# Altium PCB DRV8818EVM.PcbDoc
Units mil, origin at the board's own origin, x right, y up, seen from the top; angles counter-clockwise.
Board outline 4500 x 5500 mil, 6 copper layers (Top Layer, Kelvin, MidLayer2, GND, InternalPlane2, Bottom Layer); 107 components, 80 nets, 344 pads, 137 vias.
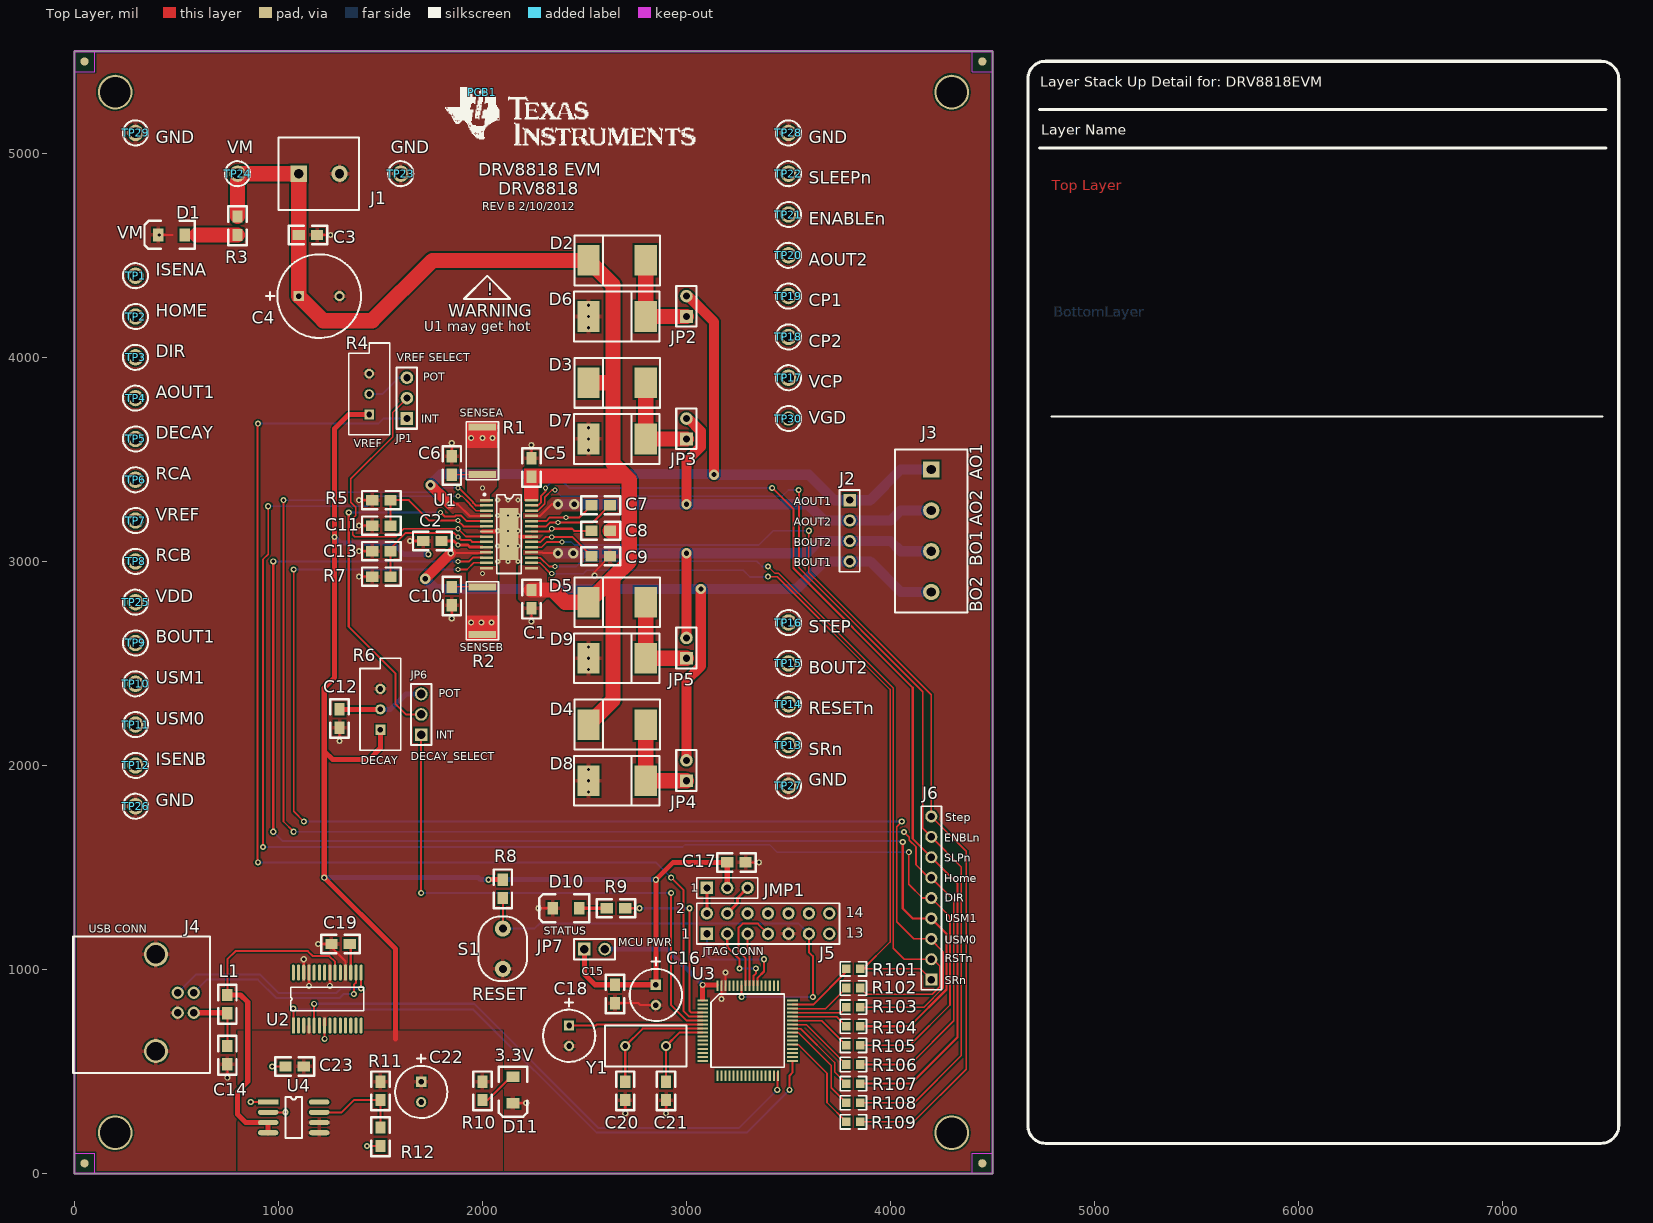
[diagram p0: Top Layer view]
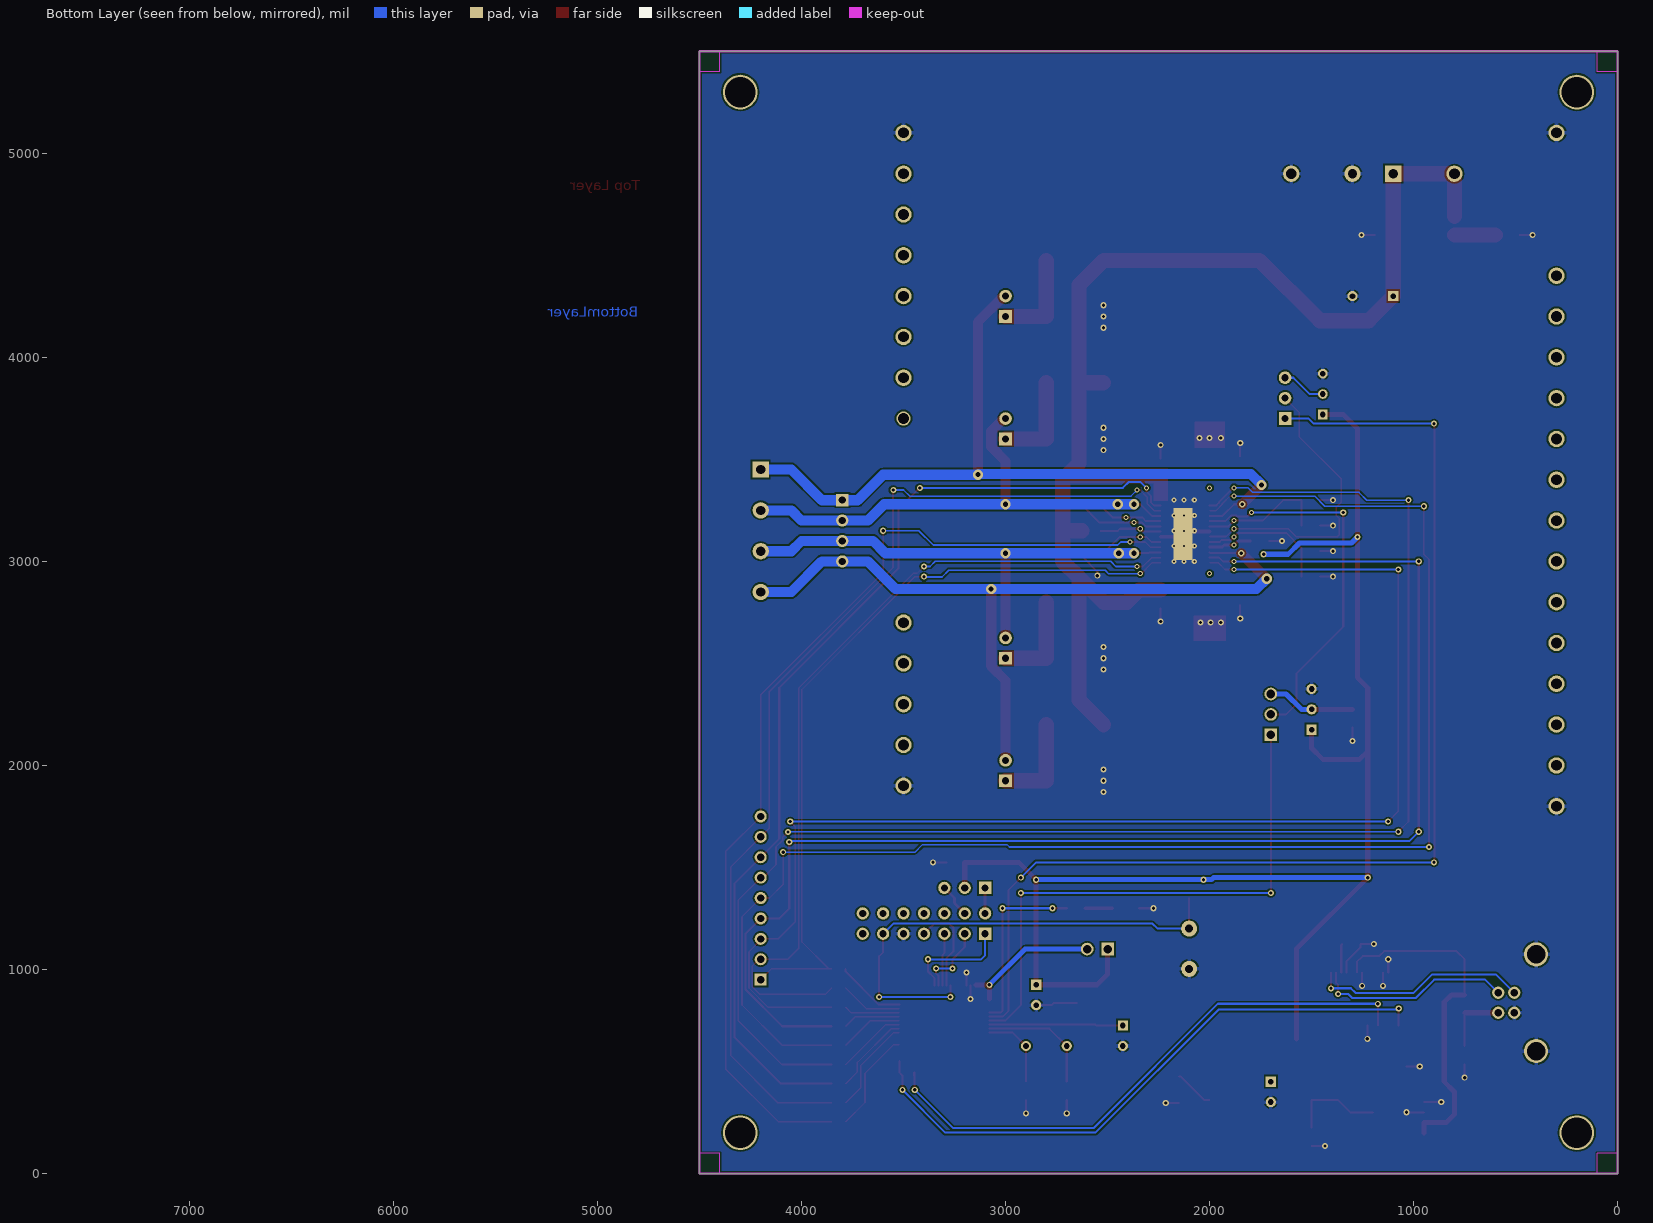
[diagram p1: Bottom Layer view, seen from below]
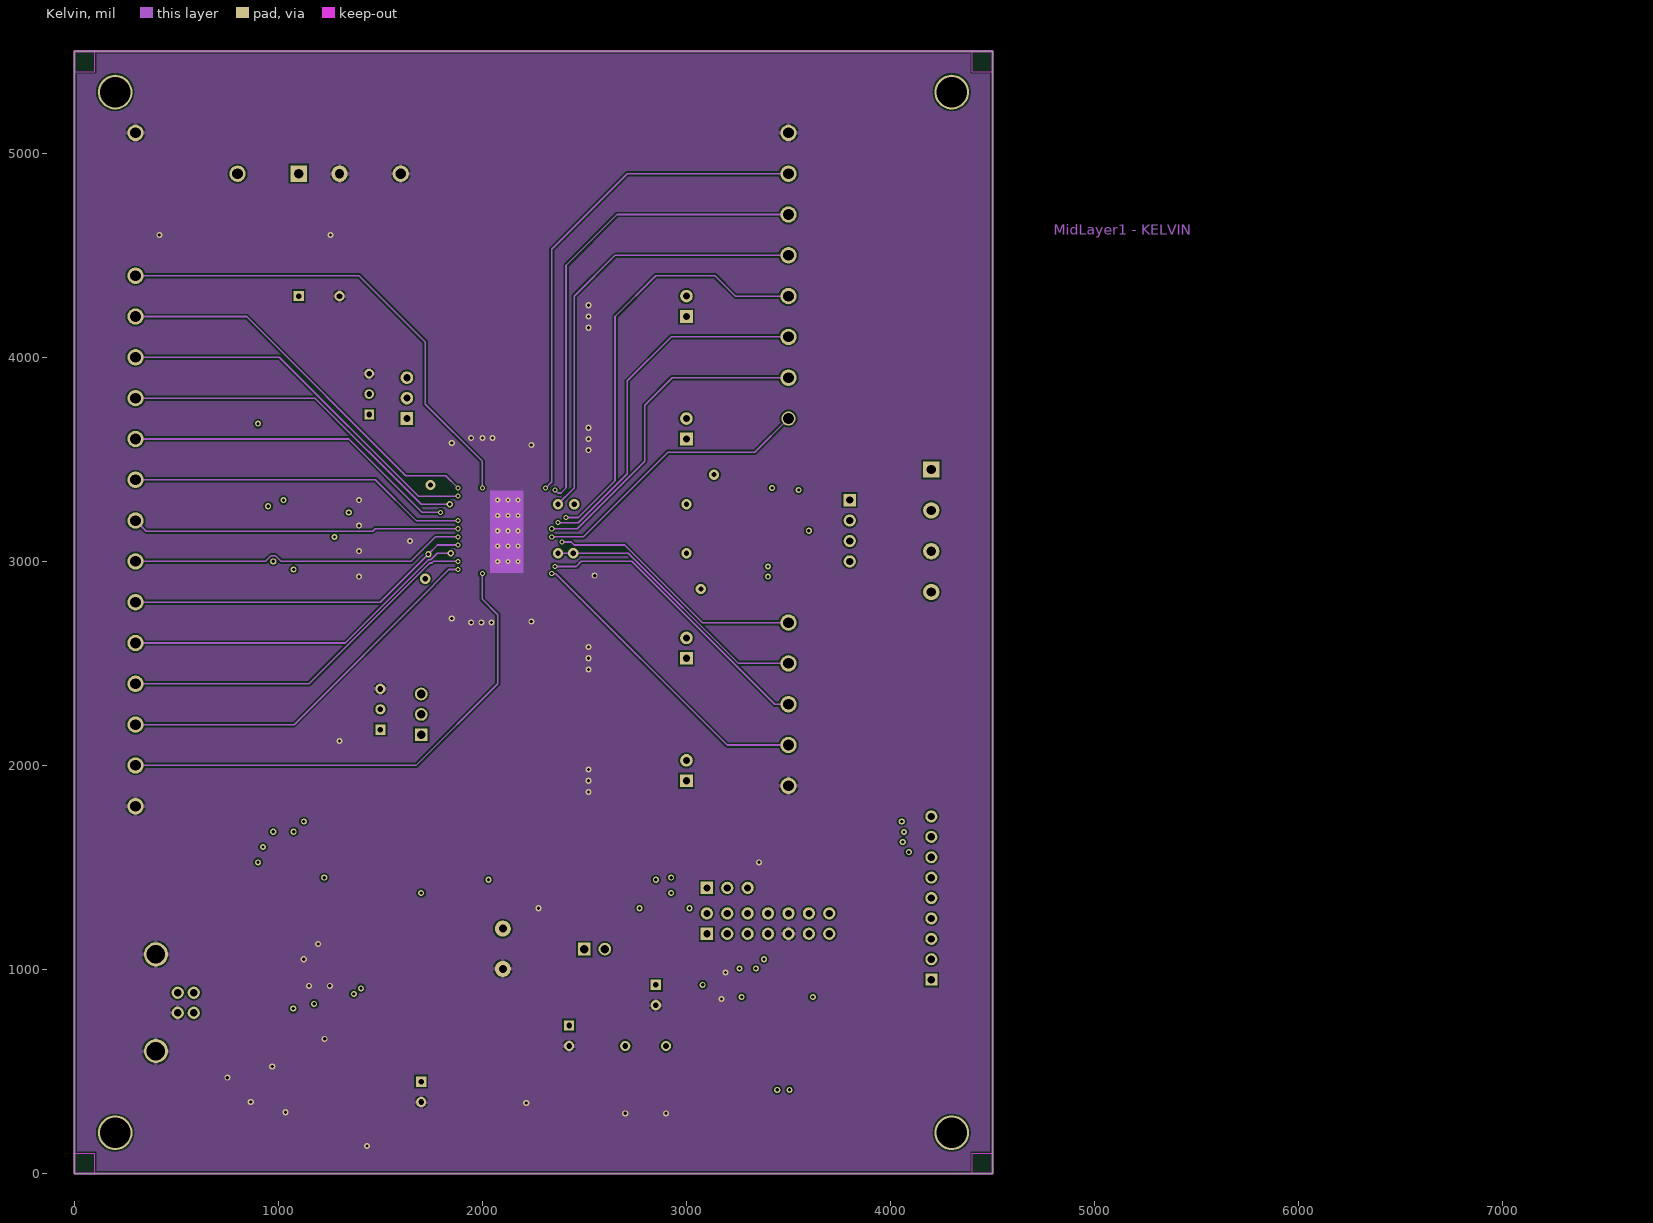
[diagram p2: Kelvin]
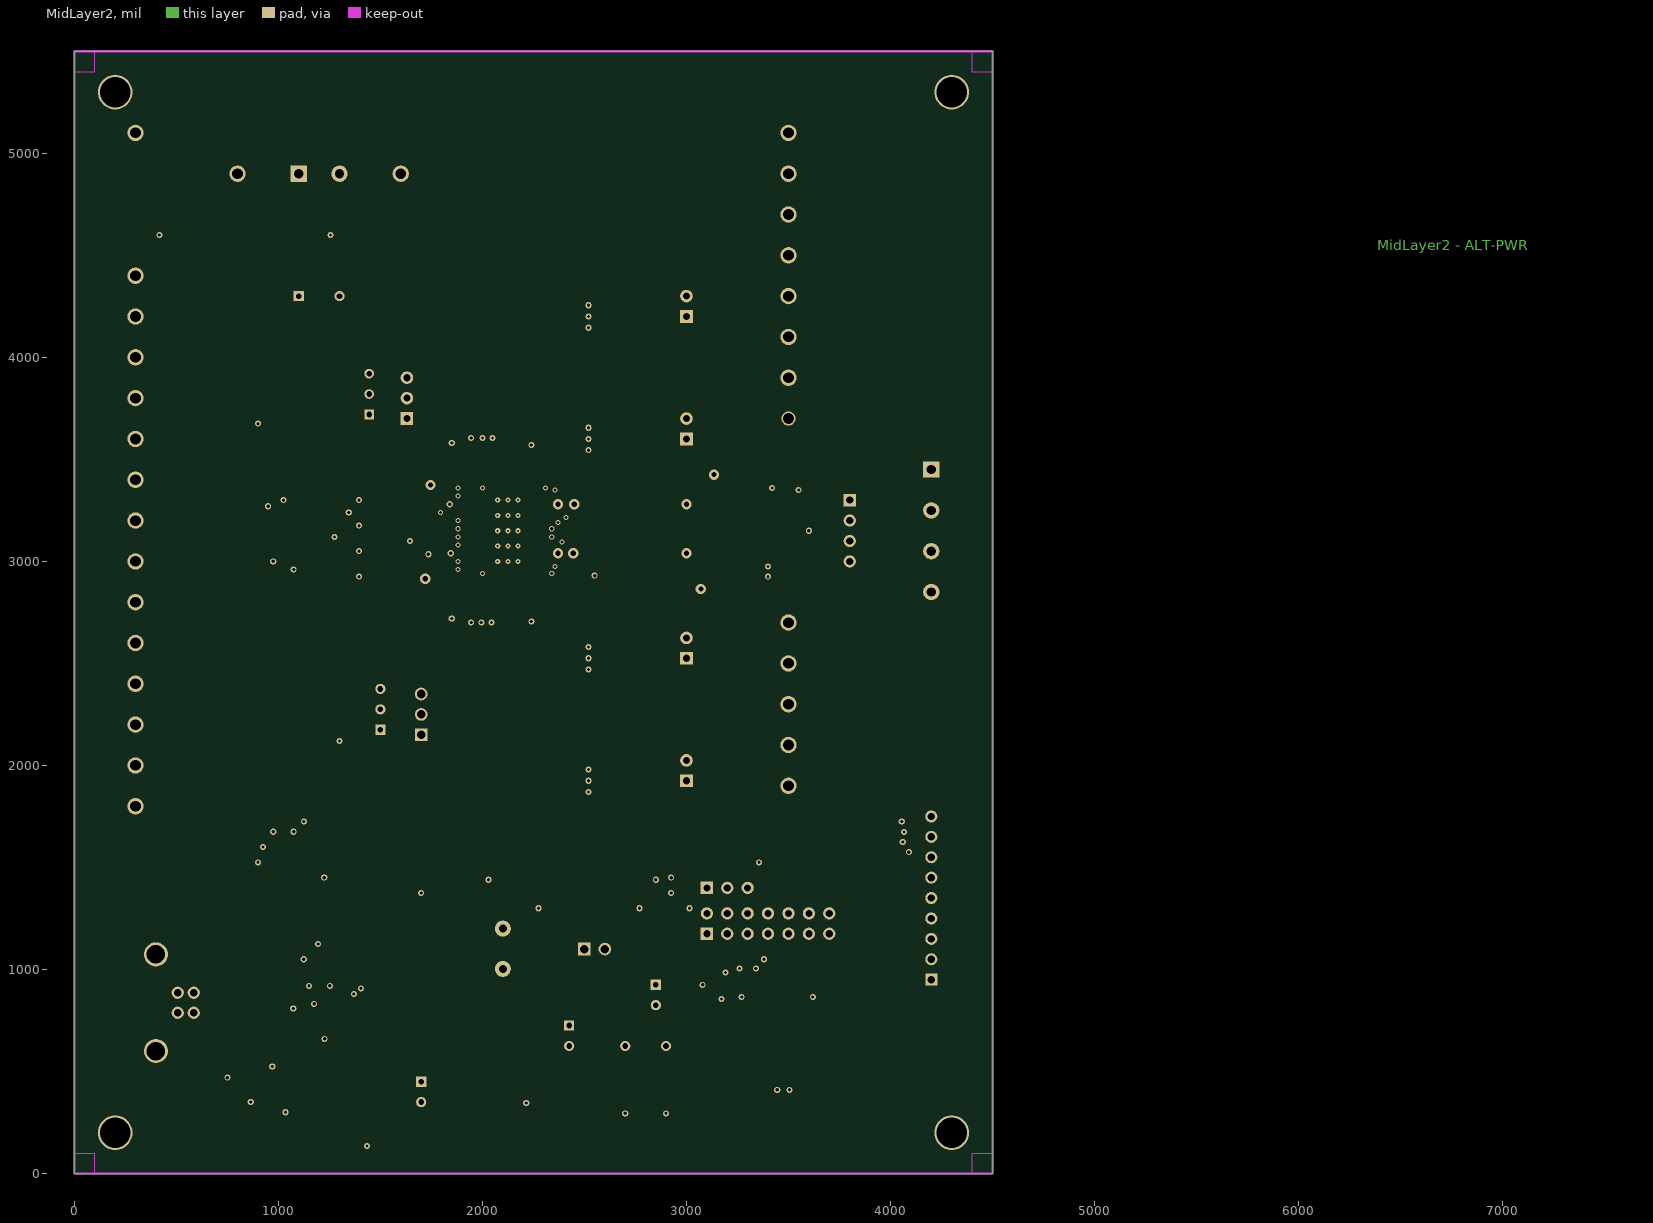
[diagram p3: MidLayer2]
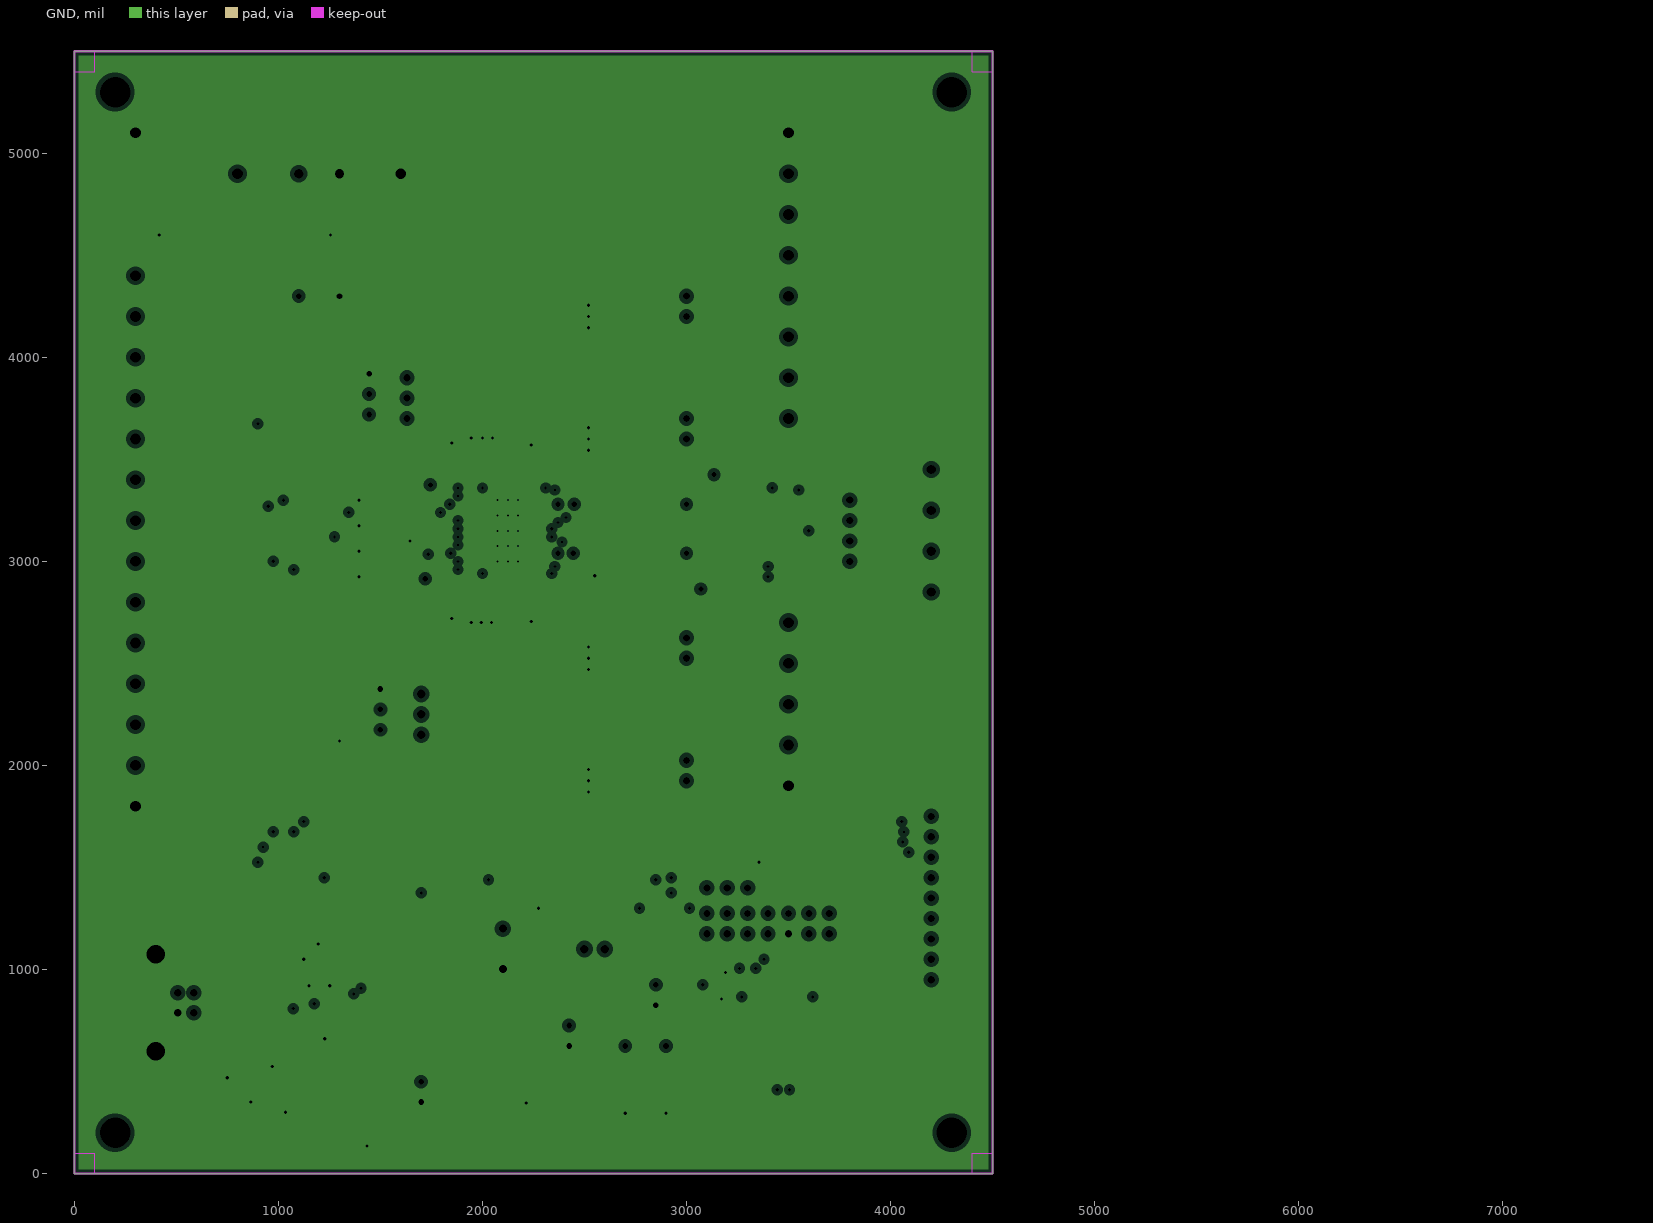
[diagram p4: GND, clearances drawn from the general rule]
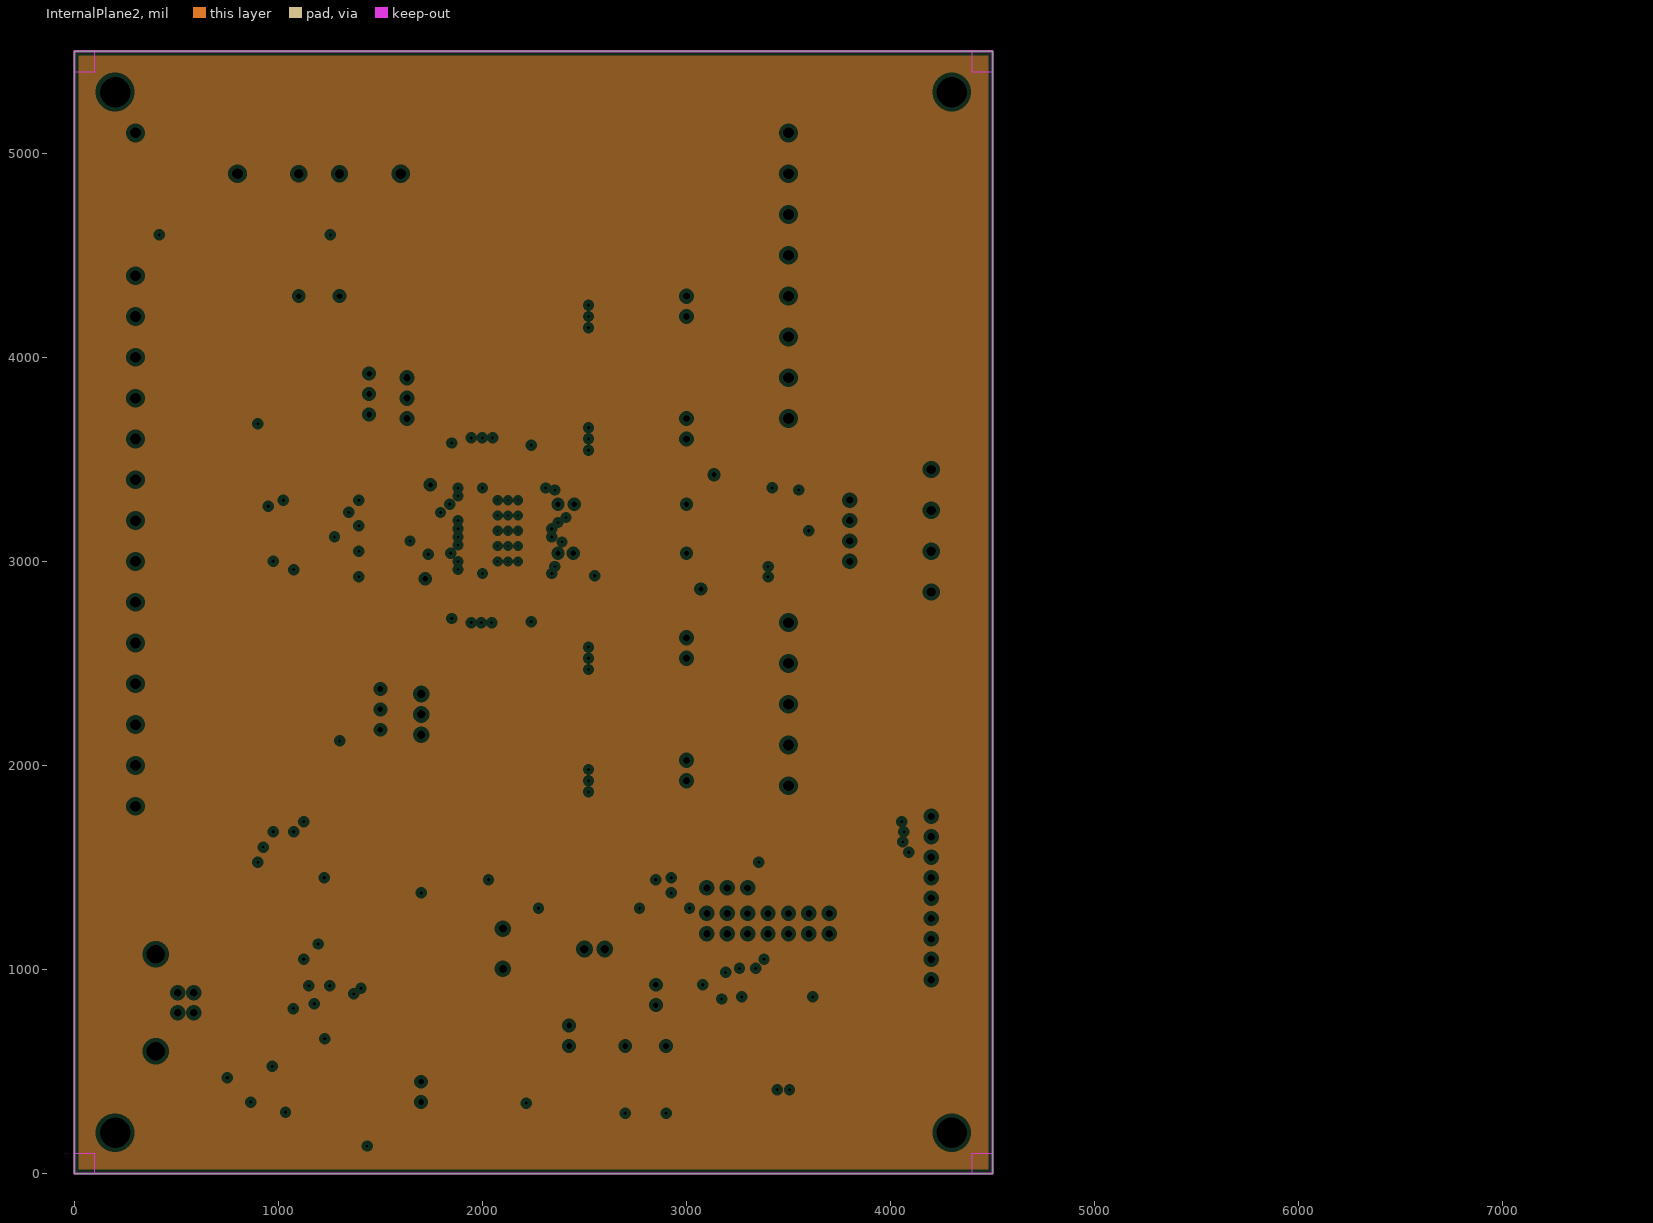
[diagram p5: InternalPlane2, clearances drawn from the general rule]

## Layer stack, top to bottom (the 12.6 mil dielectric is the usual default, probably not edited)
Top Layer: signal copper 1.4
Dielectric: core 12.6, FR-4, Dk 4.8
Kelvin: signal copper 1.4
Dielectric: prepreg 12.6, FR-4, Dk 4.8
MidLayer2: signal copper 1.4
Dielectric: dielectric 12.6, FR-4, Dk 4.8
GND: plane copper 1.4, net GND
Dielectric: core 12.6, FR-4, Dk 4.8
InternalPlane2: plane copper 1.4
Dielectric: dielectric 12.6, FR-4, Dk 4.8
Bottom Layer: signal copper 1.4

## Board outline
0,0 4500,0 4500,5500 0,5500

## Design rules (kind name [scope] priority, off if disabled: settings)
Clearance Clearance_1 [InNamedPolygon('Top Layer-MGND') Or  InNamedPolygon('Bottom Layer-OD_C_REG') Or  InNamedPolygon('Bottom Layer-OD_A_REG') Or  InNamedPolygon('Bottom Layer-OD_B_REG') Or  InNamedPolygon('Bottom Layer-MGND')] p1: gap=15
Clearance [All] p2: gap=8
HoleSize [All] p1: absolutevalues=TRUE maxlimit=360 minlimit=1 maxpercent=80.000 minpercent=20.000
MinimumAnnularRing [All] p1: minimumring=5
PlaneClearance [All] p1: clearance=20
PlaneConnect [All] p1: planeconnectstyle=Relief reliefexpansion=20 reliefentries=4 reliefconductorwidth=15 reliefairgap=10
PolygonConnect PolygonConnect_2 [(InNet('GND')) vs IsVia  or InComponent('U1')] p1: connectstyle=Direct reliefconductorwidth=10 reliefentries=4 polygonreliefangle="90 Angle"
PolygonConnect PolygonConnect_1 [All vs IsNamedPolygon('ISENA') Or  IsNamedPolygon('ISENB') Or  IsNamedPolygon('AOUT2') Or  IsNamedPolygon('BOUT2') Or  IsNamedPolygon('BOUT1') Or  IsNamedPolygon('AOUT1') Or  IsNamedPolygon('VMB') Or  IsNamedPolygon('VMA')] p2: connectstyle=Direct reliefconductorwidth=10 reliefentries=4 polygonreliefangle="90 Angle"
PolygonConnect [All] p3: connectstyle=Relief reliefconductorwidth=20 reliefentries=4 polygonreliefangle="90 Angle"
RoutingLayers [All] p1: top layer_v5=TRUE mid layer 1_v5=FALSE mid layer 2_v5=FALSE bottom layer_v5=TRUE
RoutingVias [All] p1: holewidth=16 width=30 viastyle="Through Hole" minholewidth=16 minwidth=25 maxholewidth=25 maxwidth=70
SilkscreenOverComponentPads [All] p1: minsilkscreentomaskgap=10
SolderMaskExpansion [All] p1: expansion=4
TestPointUsage [All] p1: valid=2 allowmultiple=FALSE
Testpoint [All] p1: side=15 testpointundercomponent=TRUE minsize=40 maxsize=100 preferedsize=60 minholesize=0 maxholesize=40 preferedholesize=32 testpointgrid=1 style=1023 order=0-112345678
Width [All] p1: maxlimit=100 minlimit=8 preferedwidth=8 toplayer_prefwidth=10 midlayer1_maxwidth=8 midlayer2_maxwidth=8 bottomlayer_prefwidth=50 minimp=50.000000 maximp=50.000000 favimp=50.000000
19 further rules are at their usual default settings.

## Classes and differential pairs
polygon class PinPolygons: Bottom-GND VDD

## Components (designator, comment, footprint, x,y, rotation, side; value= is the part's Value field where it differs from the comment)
C1 "" 0805 2240,2770 r90 top
C2 "" 0805 1710,3100 r0 top
C3 "" 0805 1190,4600 r180 top
C4 "" "RB .2/.4 SS" 1300,4300 r180 top
C5 "" 0805 2240,3505 r270 top
C6 "" 0805 1850,3515 r270 top
C7 ".1uF" 0805 2625,3275 r180 top
C8 ".1uF" 0805 2625,3150 r180 top
C9 ".1uF" 0805 2625,3025 r180 top
C10 "" 0805 1850,2785 r90 top
C11 "" 0805 1550,3175 r180 top
C12 "" 0805 1300,2275 r270 top
C13 "" 0805 1550,3050 r180 top
C14 "Cap" 0805 750,535 r90 top
C15 "Cap" 0805 2650,835 r90 top
C16 "Cap Pol1" "RB .1/.250" 2850,825 r270 top
C17 "Cap" 0805 3290,1525 r180 top
C18 "Cap Pol1" "RB .1/.250" 2425,625 r270 top
C19 "Cap" 0805 1260,1125 r0 top
C20 "Cap" 0805 2700,360 r90 top
C21 "Cap" 0805 2900,360 r90 top
C22 "Cap Pol1" "RB .1/.250" 1700,350 r270 top
C23 "Cap1" 0805 1035,525 r0 top
D1 "VBB" 1206_LED 540.94,4600 r180 top
D2 "MBRS360" SMC-W 2800,4475 r180 top
D3 "MBRS360" SMC-W 2800,3875 r180 top
D4 "MBRS360" SMC-W 2800,2200 r180 top
D5 "MBRS360" SMC-W 2800,2800 r180 top
D6 "MBRS360" SMC-W 2520,4200 r0 top
D7 "MBRS360" SMC-W 2520,3600 r0 top
D8 "MBRS360" SMC-W 2520,1925 r0 top
D9 "MBRS360" SMC-W 2520,2525 r0 top
D10 "LED3" 1206_LED 2475,1300 r180 top
D11 "LED3" 1206_LED 2150,475 r270 top
J1 "Header 2" PWR_CONN2 1100,4900 r0 top
J2 "Header 4" HDR1X4 3800,3300 r270 top
J3 "Header 4" PWR_CONN4 4200,3450 r270 top
J4 "USB B Conn" USB_CONN 506.69,886.22 r270 top
J5 "JTAG" HDR2X7 3100,1175 r0 top
J6 "Header 9" HDR1X9 4200,950 r90 top
JMP1 "PWR Select" HDR1X3 3100,1400 r0 top
JP1 "VREF_SELECT" JMP0.3#1 1630,3700 r90 top
JP2 "JUMPER 2 PIN" JMP0.2#1 3000,4200 r90 top
JP3 "JUMPER 2 PIN" JMP0.2#1 3000,3600 r90 top
JP4 "JUMPER 2 PIN" JMP0.2#1 3000,1925 r90 top
JP5 "JUMPER 2 PIN" JMP0.2#1 3000,2525 r90 top
JP6 "DECAY_SELECT" JMP0.3#2 1700,2150 r90 top
JP7 "MCU PWR" JMP0.2#2 2500,1100 r0 top
L1 "" 0805 750,785 r90 top
PCB1 "DRV8818" TI_LOGO 2000,5300 r0 top
R1 "" 2512 2000,3425 r90 top
R2 "" 2512 2000,2875 r270 top
R3 "Res1" 0805 800,4600 r90 top
R4 "" VR5#1 1445,3820 r90 top
R5 "" 0805 1460,3300 r0 top
R6 "" VR5#2 1500,2275 r90 top
R7 "" 0805 1460,2925 r0 top
R8 "Res1" 0805 2100,1350 r90 top
R9 "Res2" 0805 2610,1300 r0 top
R10 "Res2" 0805 2000,360 r90 top
R11 "Res2" 0805 1500,360 r90 top
R12 "Res2" 0805 1500,135 r90 top
R101 "Res2" 0603 3852,1003 r180 top
R102 "Res2" 0603 3852,909.25 r180 top
R103 "Res2" 0603 3852,815.5 r180 top
R104 "Res2" 0603 3852,721.75 r180 top
R105 "Res2" 0603 3852,628 r180 top
R106 "Res2" 0603 3852,534.25 r180 top
R107 "Res2" 0603 3852,440.5 r180 top
R108 "Res2" 0603 3852,346.75 r180 top
R109 "Res2" 0603 3852,253 r180 top
S1 "SW-PB" Pana_PB 2100,1003.15 r90 top
TP1 "ISENA" "TEST POINT 0.052"#1 300,4400 r0 top
TP2 "HOME" "TEST POINT 0.052"#1 300,4200 r0 top
TP3 "DIR" "TEST POINT 0.052"#1 300,4000 r0 top
TP4 "AOUT1" "TEST POINT 0.052"#1 300,3800 r0 top
TP5 "DECAY" "TEST POINT 0.052"#1 300,3600 r0 top
TP6 "RCA" "TEST POINT 0.052"#1 300,3400 r0 top
TP7 "VREF" "TEST POINT 0.052"#1 300,3200 r0 top
TP8 "RCB" "TEST POINT 0.052"#1 300,3000 r0 top
TP9 "BOUT1" "TEST POINT 0.052"#1 300,2600 r0 top
TP10 "USM1" "TEST POINT 0.052"#1 300,2400 r0 top
TP11 "USM0" "TEST POINT 0.052"#1 300,2200 r0 top
TP12 "ISENB" "TEST POINT 0.052"#1 300,2000 r0 top
TP13 "SRn" "TEST POINT 0.052"#1 3500,2100 r0 top
TP14 "RESETn" "TEST POINT 0.052"#1 3500,2300 r0 top
TP15 "BOUT2" "TEST POINT 0.052"#1 3500,2500 r0 top
TP16 "STEP" "TEST POINT 0.052"#1 3500,2700 r0 top
TP17 "VCP" "TEST POINT 0.052"#1 3500,3900 r0 top
TP18 "CP2" "TEST POINT 0.052"#1 3500,4100 r0 top
TP19 "CP1" "TEST POINT 0.052"#1 3500,4300 r90 top
TP20 "AOUT2" "TEST POINT 0.052"#1 3500,4500 r0 top
TP21 "ENABLEn" "TEST POINT 0.052"#1 3500,4700 r90 top
TP22 "SLEEPn" "TEST POINT 0.052"#1 3500,4900 r90 top
TP23 "GND" "TEST POINT 0.052"#1 1600,4900 r90 top
TP24 "VM" "TEST POINT 0.052"#1 800,4900 r90 top
TP25 "VDD" "TEST POINT 0.052"#1 300,2800 r90 top
TP26 "GND" "TEST POINT 0.052"#1 300,1800 r0 top
TP27 "GND" "TEST POINT 0.052"#1 3500,1900 r90 top
TP28 "GND" "TEST POINT 0.052"#1 3500,5100 r90 top
TP29 "GND" "TEST POINT 0.052"#1 300,5100 r90 top
TP30 "VGD" "TEST POINT 0.052"#2 3500,3700 r90 top
U1 "DRV8818" "HTSSOP28 - DRV8818" 2019.69,3300 r270 top
U2 "FTD232R" FT232RL 1073.23,725 r90 top
U3 "MSP430F2917" MSP430F1612 3300,700 r0 top
U4 "TPS77701" TL7726 950,350 r0 top
Y1 "8 MHZ" XTAL 2900,625 r180 top

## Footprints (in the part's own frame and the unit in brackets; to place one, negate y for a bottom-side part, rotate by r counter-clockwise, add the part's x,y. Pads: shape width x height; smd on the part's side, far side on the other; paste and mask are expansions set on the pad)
0603 [mm]
  rect 1.05x1.08 smd: 1(0,0) 2(1.73,0)
  silkscreen extent -0.77,-0.89 2.5,0.89
0805 [mil]
  rect 60x50 smd: 1(0,0) 2(90,0)
  silkscreen extent -50,-45 140,45
1206_LED [mm]
  rect 1.3x1.6 smd: 1(0,0) 2(3.3,0)
  silkscreen extent -1.25,-1.75 5,1.75
2512 [mm]
  rect 0.85x3.4 smd: 1(0,0) 2(5.93,0)
  silkscreen extent -0.64,-2 6.57,2
FT232RL [mm]
  rect 2x0.381 smd: 1(0,0)
  oval 2x0.381 smd: 2(0,-0.65) 3(0,-1.3) 4(0,-1.95) 5(0,-2.6) 6(0,-3.25) 7(0,-3.9) 8(0,-4.55) 9(0,-5.2) 10(0,-5.85) 11(0,-6.5) 12(0,-7.15) 13(0,-7.8) 14(0,-8.45) 15(6.6,-8.45) 16(6.6,-7.8) 17(6.6,-7.15) 18(6.6,-6.5) 19(6.6,-5.85) 20(6.6,-5.2) 21(6.6,-4.55) 22(6.6,-3.9) 23(6.6,-3.25) 24(6.6,-2.6) 25(6.6,-1.95) 26(6.6,-1.3) 27(6.6,-0.65) 28(6.6,0)
  silkscreen extent 1.84,-8.78 4.76,0.33
HDR1X3 [mil] "Connector; Header; 3 Position"
  rect 60x60 hole 35: 1(0,0)
  round 60 hole 35: 2(100,0) 3(200,0)
  silkscreen extent -50,-50 250,50
HDR1X4 [mil] "Connector; Header; 4 Position"
  rect 60x60 hole 35: 1(0,0)
  round 60 hole 35: 2(100,0) 3(200,0) 4(300,0)
  silkscreen extent -50,-50 350,50
HDR1X9 [mm] "Connector; Header; 9 Position"
  rect 1.5x1.5 hole 0.9: 1(0,0)
  round 1.5 hole 0.9: 2(2.54,0) 3(5.08,0) 4(7.62,0) 5(10.16,0) 6(12.7,0) 7(15.24,0) 8(17.78,0) 9(20.32,0)
  silkscreen extent -1.27,-1.27 21.59,1.27
HDR2X7 [mil] "Connector; Header; 7x2 Position"
  rect 60x60 hole 35: 1(0,0)
  round 60 hole 35: 2(0,100) 3(100,0) 4(100,100) 5(200,0) 6(200,100) 7(300,0) 8(300,100) 9(400,0) 10(400,100) 11(500,0) 12(500,100) 13(600,0) 14(600,100)
  silkscreen extent -50,-50 650,150
"HTSSOP28 - DRV8818" [mm] "Shrink Small Outline; 28 Leads; Body Width 4.4 mm; Pitch 0.65 mm"
  rect 6.46x2.35 smd: 0(4.225,2.8)
  rect 6.46x2.35 smd far side: 0(4.225,2.8)
  rect 0.3x1.6 smd: 1(0,0) 2(0.65,0) 3(1.3,0) 4(1.95,0) 5(2.6,0) 6(3.25,0) 7(3.9,0) 8(4.55,0) 9(5.2,0) 10(5.85,0) 11(6.5,0) 12(7.15,0) 13(7.8,0) 14(8.45,0) 15(8.45,5.6) 16(7.8,5.6) 17(7.15,5.6) 18(6.5,5.6) 19(5.85,5.6) 20(5.2,5.6) 21(4.55,5.6) 22(3.9,5.6) 23(3.25,5.6) 24(2.6,5.6) 25(1.95,5.6) 26(1.3,5.6) 27(0.65,5.6) 28(0,5.6)
  silkscreen extent -0.82,-0.37 9.13,4.35
JMP0.2#1 [mil]
  rect 62x62 hole 35: 1(0,0)
  round 62 hole 35: 2(100,0)
  silkscreen extent -50,-50 150,50
JMP0.2#2 [mil]
  rect 62x62 hole 42: 1(0,0)
  round 62 hole 42: 2(100,0)
  silkscreen extent -50,-50 150,50
JMP0.3#1 [mil]
  rect 62x62 hole 35: 1(0,0)
  round 62 hole 35: 2(100,0) 3(200,0)
  silkscreen extent -50,-50 250,50
JMP0.3#2 [mil]
  rect 62x62 hole 42: 1(0,0)
  round 62 hole 42: 2(100,0) 3(200,0)
  silkscreen extent -50,-50 250,50
MSP430F1612 [mm]
  rect 1.35x0.25 smd: 1(-5.6,3.75) 2(-5.6,3.25) 3(-5.6,2.75) 4(-5.6,2.25) 5(-5.6,1.75) 6(-5.6,1.25) 7(-5.6,0.75) 8(-5.6,0.25) 9(-5.6,-0.25) 10(-5.6,-0.75) 11(-5.6,-1.25) 12(-5.6,-1.75) 13(-5.6,-2.25) 14(-5.6,-2.75) 15(-5.6,-3.25) 16(-5.6,-3.75) 33(5.6,-3.75) 34(5.6,-3.25) 35(5.6,-2.75) 36(5.6,-2.25) 37(5.6,-1.75) 38(5.6,-1.25) 39(5.6,-0.75) 40(5.6,-0.25) 41(5.6,0.25) 42(5.6,0.75) 43(5.6,1.25) 44(5.6,1.75) 45(5.6,2.25) 46(5.6,2.75) 47(5.6,3.25) 48(5.6,3.75)
  rect 0.25x1.35 smd: 17(-3.75,-5.6) 18(-3.25,-5.6) 19(-2.75,-5.6) 20(-2.25,-5.6) 21(-1.75,-5.6) 22(-1.25,-5.6) 23(-0.75,-5.6) 24(-0.25,-5.6) 25(0.25,-5.6) 26(0.75,-5.6) 27(1.25,-5.6) 28(1.75,-5.6) 29(2.25,-5.6) 30(2.75,-5.6) 31(3.25,-5.6) 32(3.75,-5.6) 49(3.75,5.6) 50(3.25,5.6) 51(2.75,5.6) 52(2.25,5.6) 53(1.75,5.6) 54(1.25,5.6) 55(0.75,5.6) 56(0.25,5.6) 57(-0.25,5.6) 58(-0.75,5.6) 59(-1.25,5.6) 60(-1.75,5.6) 61(-2.25,5.6) 62(-2.75,5.6) 63(-3.25,5.6) 64(-3.75,5.6)
  silkscreen extent -4.56,-4.56 4.56,4.56
Pana_PB [mm] "Panasonic EVQ-11A04M Push Button"
  round 2 hole 1: 1(0,0) 2(5,0)
  silkscreen extent -1.51,-3 6.51,3
PWR_CONN2 [mil]
  rect 80x80 hole 45: 1(0,0)
  round 80 hole 45: 2(200,0)
  silkscreen extent -98,-177 295,177
PWR_CONN4 [mil]
  rect 80x80 hole 45: 1(0,0)
  round 80 hole 45: 2(200,0) 3(400,0) 4(600,0)
  silkscreen extent -98,-177 700,177
"RB .1/.250" [mil]
  rect 50x50 hole 28: 1(-100,0)
  round 50 hole 28: 2(0,0)
  silkscreen extent -234,-128 78,128
"RB .2/.4 SS" [mil] "Reduced Size Footprint (Plus is closer to Body for better Clearance)"
  rect 50x50 hole 28: 1(200,0)
  round 50 hole 28: 2(0,0)
  silkscreen extent -105,-205 360,205
SMC-W [mil]
  rect 110x150 smd: 1(0,0) 2(280,0)
  silkscreen extent -70,-122 349,122
"TEST POINT 0.052"#1 [mil] "Glass Beaded Test Point"
  round 80 hole 52: 1(0,0)
  silkscreen extent -61,-61 62,61
"TEST POINT 0.052"#2 [mil] "Glass Beaded Test Point"
  round 70 hole 52: 1(0,0)
  silkscreen extent -61,-62 61,61
TI_LOGO [mil] "Texas Instruments Logo"
  silkscreen extent -181,-261 1042,25
TL7726 [mil]
  rect 100x25 smd: 1(0,0)
  oval 100x25 smd: 2(0,-50) 3(0,-100) 4(0,-150) 5(250,-150) 6(250,-100) 7(250,-50) 8(250,0)
  silkscreen extent 85,-175 165,25
USB_CONN [mm] "USB Right Angle receptacle"
  round 1.524 hole 0.889: 1(2.5,2) 2(0,2) 3(0,0) 4(2.5,0)
  round 3 hole 2.3: 5(-4.77,-2.71) 6(7.27,-2.71)
  silkscreen extent -7,-13 10,4
VR5#1 [mm] "Potentiometer; 3 Leads"
  rect 1.2x1.2 hole 0.711: 1(-2.54,0)
  round 1.2 hole 0.711: 2(0,0) 3(2.54,0)
  silkscreen extent -5.08,-2.54 6.35,2.54
VR5#2 [mm] "Potentiometer; 3 Leads"
  rect 1.27x1.27 hole 0.711: 1(-2.54,0)
  round 1.27 hole 0.711: 2(0,0) 3(2.54,0)
  silkscreen extent -5.08,-2.54 6.35,2.54
XTAL [mil]
  round 50 hole 28: 1(0,0) 2(200,0)
  silkscreen extent -100,-100 300,100

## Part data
C1 C2 C3 C5 C6 C7 C8 C9 C10 C11 C12 C13 C18: library part Cap, "Capacitor"
C4: library part "Cap Pol1", "Polarized Capacitor (Radial)"
C14 C15 C17 C19 C21 C23: "Capacitor"
C16 C22: "Polarized Capacitor (Radial)"
C20: library part Cap1, "Capacitor"
D1: library part LED3, "Red LED 1206"
D2 D3 D4 D5 D6 D7 D8 D9: library part "D Schottky", "Schottky Diode"
D10 D11: "LED RED Clear 1206 SMD"
J1: "Header, 2-Pin"
J2 J3: "Header, 4-Pin"
J4: library part USB_B_CONN, "USB B Style Connector"
J5: library part "Header 7X2H", "Header, 7-Pin, Dual row, Right Angle"
J6: "Control"
JMP1: library part "Header 3", "Header, 3-Pin"
JP1 JP6: library part "JUMPER 3 PIN", "Three Pin Jumper"
JP2 JP3 JP4 JP5: "Two Pin Jumper"
JP7: library part "JUMPER 2 PIN", "Single Line, 2 Pos, 100 mil pitch Header Connector"
L1: library part Inductor, "Ferrite Bead 1.5A 40 ohm 0805 SMD"
PCB1: library part TI_LOGO, "TI Silkscreen Logo"
R1 R2 R5 R7: library part Res1, "Resistor"
R3 R8 R9 R10 R11 R12 R101 R102 R103 R104 R105 R106 R107 R108 R109: "Resistor"
R4 R6: library part RPot, "Potentiometer"
S1: "Switch"
TP1 TP2 TP3 TP4 TP5 TP6 TP7 TP8 TP9 TP10 TP11 TP12 TP13 TP14 TP15 TP16 TP17 TP18 TP19 TP20 TP21 TP22 TP23 TP24 TP25 TP26 TP27 TP28 TP29 TP30: library part "TEST POINT", "Glass Beaded Test Point"
U1: library part DRV8811, "Stepper Indexer"
U2: library part FT232R, "USB Chip"
U3: library part MSP430F1612, "MSp430 Microcontroller"
U4: "750 mA LDO 8-SOIC"
Y1: library part XTAL, "Crystal Oscillator"

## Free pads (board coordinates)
  round 40 smd: 0(50,50) 0(50,5450) 0(4450,50) 0(4450,5450)
  round 170 hole 150: 0(200,200) 0(200,5300) 0(4300,200) 0(4300,5300)

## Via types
v1: diameter 30, hole 16, Top Layer to Bottom Layer, 92 vias
v2: diameter 25, hole 15, Top Layer to Bottom Layer, 20 vias
v3: diameter 25, hole 10, Top Layer to Bottom Layer, 15 vias
v4: diameter 50, hole 25, Top Layer to Bottom Layer, 10 vias

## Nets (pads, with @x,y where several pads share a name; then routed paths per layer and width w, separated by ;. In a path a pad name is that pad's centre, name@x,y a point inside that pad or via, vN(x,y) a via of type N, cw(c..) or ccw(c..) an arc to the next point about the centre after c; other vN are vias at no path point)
5VCC: L1.2 U2.20 U4.3 U4.4 | length 1695.4
  Top Layer w10: L1.2 750,1050 790,1090 1145,1090 1170,1065 1250,1065 1277.95,1037.05 U2.20
  Top Layer w25: L1.2 815,875 850,840 850,450 800,400 800,290 840,250 U4.3 U4.4
AOUT1: J2.1 J3.1 JP2.2 TP4.1 U1.4 | length 5605.6
  Top Layer w10: v1(1840,3280) 1880,3280 1936.77,3223.23 U1.4@2000,3223.23
  Top Layer w50: v4(1745,3375) v1(1840,3280) ; JP2.2 3008.67,4300 3135,4173.67 v4(3135,3425)
  Kelvin w8: TP4.1 1180,3800 1700,3280 v1(1840,3280)
  Bottom Layer w50: v4(1745,3375) 1798,3428 3132,3428 v4(3135,3425) 3600,3425 3725,3300 J2.1 3900,3300 4050,3450 J3.1 ; JP2.2@2997,4303 JP2.2
AOUT2: J2.2 J3.2 JP3.2 TP20.1 U1.25 | length 4706.7
  Top Layer w10: U1.25 2283.23,3223.23 2340,3280 v4(2370,3280)
  Top Layer w50: v4(3000,3280) 3000,3491.33 3070.5,3561.83 3070.5,3638.17 3008.67,3700 JP3.2
  Kelvin w8: v4(2370,3280) 2450,3360 2450,4300 2650,4500 TP20.1
  Bottom Layer w50: v4(2370,3280) v4(2450,3280) v4(3000,3280) 3595,3280 3675,3200 J2.2 4000,3200 4050,3250 J3.2
BOUT1: J2.4 J3.4 JP4.2 TP9.1 U1.11 | length 5552.4
  Top Layer w10: v1(1845,3040) 1995.91,3040 U1.11@2000,3044.09
  Top Layer w50: v4(1720,2915) v1(1845,3040) ; JP4.2 3000,2416.33 3070.5,2486.83 v4(3070.5,2864.5)
  Kelvin w8: TP9.1 1327.37,2600 1735.37,3008 1746.18,3008 1778.18,3040 v1(1845,3040)
  Bottom Layer w50: v4(1720,2915) 1770,2865 3070.5,2865 3540,2865 3675,3000 J2.4 3900,3000 4050,2850 J3.4 ; JP4.2@2997,2028 JP4.2
BOUT2: J2.3 J3.3 JP5.2 TP15.1 U1.18 | length 3775.8
  Top Layer w10: U1.18 2294.09,3044.09 2298.19,3040 v4(2370,3040)
  Top Layer w50: JP5.2 v4(3000,3040)
  Kelvin w8: v4(2370,3040) v4(2445,3040) 2714.75,3040 3254.75,2500 TP15.1
  Bottom Layer w50: v4(2370,3040) v4(2445,3040) v4(3000,3040) 3589,3040 3649,3100 J2.3 4000,3100 4050,3050 J3.3
CBUS0: U2.23
CBUS1: U2.22
CBUS2: U2.13
CBUS3: U2.14
CBUS4: U2.12
CP1: C7.2 TP19.1 U1.24 | length 2420.4
  Top Layer w10: U1.24 2312.64,3197.64 2330.5,3215.5 v2@2409.5,3215.5 ; v2(2410,3215) 2475,3215 C7.2
  Kelvin w8: v2(2410,3215) 2470,3215 2650,3395 2650,4200 2850,4400 3140,4400 3240,4300 TP19.1
CP2: C7.1 TP18.1 U1.23 | length 2201.4
  Top Layer w10: U1.23 2312.5,3172.05 2330.46,3190 v2(2370,3190) 2370.5,3189.5 2539.5,3189.5 C7.1
  Kelvin w8: v2(2370,3190) 2470,3190 2710,3430 2710,3885 2925,4100 TP18.1
CTS: U2.11
DCD: U2.10
DECAY: JP6.2 TP5.1 U1.5 | length 3502.2
  Top Layer w10: v1(1345,3240) 1345,2680 1575,2450 1575,2300 1625,2250 JP6.2 ; v2(1795,3240) 1815,3220 1863.94,3220 1869.44,3225.5 1894.5,3225.5 1922.36,3197.64 U1.5@2000,3197.64
  Kelvin w8: TP5.1 1345,3600 1705,3240 v2(1795,3240)
  Bottom Layer w10: v1(1345,3240) v2(1795,3240)
DIR: J6.5 R105.1 TP3.1 U1.3 | length 9208.7
  Top Layer w8: v1(925,1600) 925,3010 950,3035 v1(950,3270) ; v2(1880,3320) 1900,3320 1937.52,3282.48 1937.52,3279.56 1968.26,3248.82 U1.3@2000,3248.82 ; R105.1 4094,628 4291.53,825.53 4291.53,1258.47 J6.5 4157,1350 4090,1417 v1(4090,1575)
  Kelvin w8: TP3.1 1005,4000 1685,3320 v2(1880,3320)
  Bottom Layer w8: v1(925,1600) 2980.96,1600 2992.96,1612 3407.04,1612 3444.04,1575 v1(4090,1575) ; v1(950,3270) 1435,3270 1485,3320 v2(1880,3320)
DSR: U2.9
DTR: U2.2
ENABLEN: J6.8 R108.1 TP21.1 U1.26 | length 7442.4
  Top Layer w8: U1.26 2271.89,3248.82 2305,3281.93 2305,3313.66 2341.34,3350 v2(2355,3350) ; v1(3550,3350) 3551.68,3348.32 3551.68,2968.32 4158.47,2361.53 4158.47,1691.53 J6.8 4346,1504 4346,577 4115.75,346.75 R108.1
  Kelvin w8: v2(2355,3350) 2370,3335 2385,3335 2410,3360 2410,4450 2660,4700 TP21.1
  Bottom Layer w8: v2(2355,3350) 2385,3320 3470,3320 3500,3350 v1(3550,3350)
GDECAY: JP6.1 U3.6 | length 2735.9
  Top Layer w10: v1(1700,1375) JP6.1 ; v1(2925,1375) 2925,825 3000.79,749.21 U3.6
  Bottom Layer w10: v1(1700,1375) v1(2925,1375)
GND: C1.1 C2.1 C3.1 C4.2 C5.1 C6.1 C9.1 C10.1 C11.2 C12.2 C13.2 C14.1 C15.1 C16.2 C17.1 C18.2 C19.1 C20.1 C21.1 C22.2 C23.1 D1.2 D6.1 D7.1 D8.1 D9.1 D10.2 D11.2 J1.2 J4.4 J4.5 J4.6 J5.9 R1.2 R2.2 R4.3 R5.1 R6.3 R7.1 R12.1 S1.1 TP23.1 TP26.1 TP27.1 TP28.1 TP29.1 U1.0 U1.7 U1.21 U2.7 U2.18 U2.21 U2.25 U2.26 U3.62 U3.63 U4.1 U4.2 | length 2679.8
  Top Layer w10: v1(416.89,4600) 481.89,4600 ; v1(750,470) C14.1 ; v1(865,350) U4.1 ; U4.2 v1(1035,300) ; v1(970,525) C23.1 ; U2.26 v1(1124.41,1049.84) ; v1(1150,919.84) U2.25 ; C3.1 v1(1255,4600) ; v1(1195,1125) C19.1 1260,1110 1329.13,1040.87 U2.18 ; v1(1226.77,660) U2.7 ; v1(1252.36,919.84) U2.21 ; v1(1300,2120) C12.2 ; v1(1395,2925) R7.1 ; v1(1395,3050) C13.2 ; v1(1395,3175) C11.2 ; v1(1395,3300) R5.1 ; v1(1435,135) R12.1 ; v1(1645,3100) C2.1 ; v1(1850,2720) C10.1 ; C6.1 v1(1850,3580) ; U1.0@2107.28,3146.46 2114.37,3139.37 2125,3128.74 U1.0@2132.87,3120.87 ; D11.2 v1(2215,345.08) ; v1(2240,2705) C1.1 ; C5.1 v1(2240,3570) ; v1(2275,1300) D10.2 ; v1(2550,2930) 2550,2950 C9.1 ; C15.1 2765,835 2775,825 C16.2 ; v1(2700,295) C20.1 ; v1(2900,295) C21.1 ; v1(3172.05,855.47) U3.63 ; U3.62 v1(3191.73,985.47) ; C17.1 v1(3355,1525)
  Top Layer w18: U1.7@2000,3146.46 U1.7 2075,3146.46 U1.0@2107.28,3146.46 ; U1.0@2132.87,3120.87 U1.21
  other v1: 2520,1870 2520,1925 2520,1980 2520,2470 2520,2525 2520,2580 1945,2700 1995,2700 2045,2700 2520,3545 2520,3600 1945,3605 2000,3605 2050,3605 2520,3655 2520,4145 2520,4200 2520,4255
  other v3: 2075,3000 2125,3000 2175,3000 2075,3075 2125,3075 2175,3075 2075,3150 2125,3150 2175,3150 2075,3225 2125,3225 2175,3225 2075,3300 2125,3300 2175,3300
GVREF: JP1.1 U3.5 | length 5732.5
  Top Layer w10: v1(900,1525) 897,1528 897,3672 v1(900,3675) ; v1(2925,1450) 2985,1390 2985,797.79 3013.9,768.9 U3.5
  Bottom Layer w10: v1(900,1525) 2850,1525 v1(2925,1450) ; v1(900,3675) 1490,3675 1515,3700 JP1.1
HOME: J6.6 R106.1 TP2.1 U1.2 | length 9182.9
  Top Layer w8: v1(1025,3300) 1025,1725 v1(1075,1675) ; R106.1 4096.25,534.25 4310,748 4310,1340 J6.6 4187.55,1450 4124.77,1512.77 4124.77,1601.19 4092,1633.96 4092,1648 v1(4066,1674)
  Top Layer w10: v2(1880,3360) 1884.04,3360 1954.52,3289.52 1954.52,3286.74 1966.85,3274.41 U1.2@2000,3274.41
  Kelvin w8: TP2.1 845,4200 1625,3420 1820,3420 v2(1880,3360)
  Bottom Layer w8: v1(1025,3300) 1230,3300 1268,3338 1788,3338 1810,3360 v2(1880,3360) ; v1(1075,1675) 4065,1675 v1(4066,1674)
ISENA: C6.2 R1.1 TP1.1 U1.1 | length 2535.6
  Top Layer w8: C6.2 R1.1
  Kelvin w8: TP1.1 1395,4400 1720,4075 1720,3770 2000,3490 v2(2000,3360)
ISENB: C10.2 R2.1 TP12.1 U1.14 | length 2661.8
  Top Layer w8: C10.2 R2.1
  Kelvin w8: TP12.1 1675,2000 2075,2400 2075,2738.75 2000,2813.75 v2(2000,2940)
NetC12_1: C12.1 JP6.3 R6.2 | length 431.1
  Top Layer w25: C12.1 R6.2
  Bottom Layer w25: R6.2 1550,2275 1625,2350 JP6.3
NetC14_2: C14.2 J4.1 L1.1 | length 325.7
  Top Layer w10: L1.1@747.2,787.8 L1.1 C14.2
  Top Layer w25: J4.1 L1.1@747.2,787.8
NetC18_1: C18.1 U3.7 | length 656.4
  Top Layer w10: C18.1 2555,725 2559.53,729.53 U3.7
NetC19_2: C19.2 U2.17 | length 142.1
  Top Layer w10: C19.2 1354.72,1120.28 U2.17
NetC20_2: C20.2 U3.8 Y1.2 | length 589.7
  Top Layer w10: C20.2 Y1.2 2784.84,709.84 U3.8
NetC21_2: C21.2 U3.9 Y1.1 | length 381.5
  Top Layer w10: C21.2 Y1.1 2965.16,690.16 U3.9
NetD1_1: D1.1 R3.1 | length 200
  Top Layer w75: 600,4600 R3.1
NetD2_1: D2.1 D6.2 JP2.1 | length 475
  Top Layer w75: D2.1 D6.2 JP2.1
NetD3_1: D3.1 D7.2 JP3.1 | length 475
  Top Layer w75: D3.1 D7.2 JP3.1
NetD4_1: D4.1 D8.2 JP4.1 | length 475
  Top Layer w75: D4.1 D8.2 JP4.1
NetD5_1: D5.1 D9.2 JP5.1 | length 475
  Top Layer w75: D5.1 D9.2 JP5.1
NetD10_1: D10.1 R9.1 | length 135
  Top Layer w15: D10.1 R9.1
NetD11_1: D11.1 R10.1 | length 197.6
  Top Layer w10: R10.1 2025,360 2140,475 D11.1
NetJ5_1: J5.1 U3.54 | length 535.6
  Top Layer w10: U3.54 3349.21,959.21 3380,990 v1(3380,1050)
  Bottom Layer w10: J5.1 3100,1070 3120,1050 v1(3380,1050)
NetJ5_2: J5.2 JMP1.1 | length 125
  Top Layer w15: J5.2 JMP1.1
NetJ5_3: J5.3 U3.55 | length 363.7
  Top Layer w10: J5.3 3200,1110 3260,1050 v1(3260,1005) ; U3.55 3329.53,969.53 3340,980 v1(3340,1005)
  Bottom Layer w10: v1(3260,1005) v1(3340,1005)
NetJ5_4: J5.4 JMP1.3 | length 166.4
  Top Layer w15: J5.4 3250,1325 3250,1350 JMP1.3
NetJ5_5: J5.5 U3.56 | length 258.6
  Top Layer w10: J5.5 3300,1080 3309.84,1070.16 U3.56
NetJ5_7: J5.7 U3.57 | length 542.6
  Top Layer w10: 3290.16,990 U3.57 3290.16,1054.84 3255,1090 3255,1205 3275,1225 3350,1225 J5.7
NetJP1_3: JP1.3 R4.2 | length 218.1
  Bottom Layer w10: R4.2 1510,3820 1590,3900 JP1.3
NetJP7_2: JP7.2 U3.1 U3.64 | length 687.2
  Top Layer w25: 3079.53,855 v1(3079.53,924.53) 3145,924.53
  Bottom Layer w25: JP7.2 2904.06,1100 v1(3079.53,924.53)
NetR11_1: R11.1 R12.2 U4.7 | length 459.9
  Top Layer w10: U4.7 1310,300 1370,360 R11.1 R12.2
NetR101_2: R101.2 U3.47 | length 343.4
  Top Layer w10: U3.47 3621.61,827.95 3783.89,990.24 R101.2
NetR102_2: R102.2 U3.46 | length 305.2
  Top Layer w8: U3.46 3682.91,808.27 R102.2
NetR103_2: R103.2 U3.45 | length 274.6
  Top Layer w8: U3.45 3756.97,788.58 R103.2
NetR104_2: R104.2 U3.44 | length 282.9
  Top Layer w8: U3.44 3736.74,768.9 R104.2
NetR105_2: R105.2 U3.43 | length 313.6
  Top Layer w8: U3.43 3662.68,749.21 R105.2
NetR106_2: R106.2 U3.42 | length 344.3
  Top Layer w8: U3.42 3588.61,729.53 R106.2
NetR107_2: R107.2 U3.41 | length 401.7
  Top Layer w8: U3.41 3560.16,709.84 3726,544 3726,498.39 R107.2
NetR108_2: R108.2 U3.40 | length 469.4
  Top Layer w8: U3.40 3549.25,690.16 3710,529.41 3710,420.64 R108.2
NetR109_2: R109.2 U3.37 | length 504.1
  Top Layer w8: U3.37 3549.25,631.1 3689,491.36 3689,347.89 R109.2
OSCI: U2.27
OSCO: U2.28
P6M5: R9.2 U3.4 | length 885.9
  Top Layer w10: R9.2 v1(2770,1300) ; v1(3015,1300) 3015,797.16 3023.58,788.58 U3.4
  Bottom Layer w10: v1(2770,1300) v1(3015,1300)
RCA: C11.1 R5.2 TP6.1 U1.6 | length 2290.8
  Top Layer w10: C11.1 R5.2 1640,3300 1740,3200 v2(1880,3200) 1907.95,3172.05 U1.6@2000,3172.05
  Kelvin w8: TP6.1 1475,3400 1675,3200 v2(1880,3200)
RCB: C13.1 R7.2 TP8.1 U1.9 | length 2291.7
  Top Layer w10: R7.2 C13.1 1550,3065 1625,3140 1860,3140 v2(1880,3120) 1895,3105 1940.55,3105 1950.28,3095.28 U1.9@2000,3095.28
  Kelvin w8: TP8.1 936.82,3000 963.82,3027 986.18,3027 1013.18,3000 1650,3000 1770,3120 v2(1880,3120)
RESET: U2.19
RESETN: J6.2 R102.1 TP14.1 U1.17 | length 5562.2
  Top Layer w8: U1.17 2283.5,3018.5 2327.01,2975 v2(2355,2975) ; v1(3400,2975) 3434,2941 3451.98,2941 4014,2378.98 4014,1104.05 4068.05,1050 J6.2 4209,1050 4241.53,1017.47 4241.53,915.5 4205.03,879 3882.25,879 R102.1
  Kelvin w8: v2(2355,2975) 2460,2975 2485,3000 2732.12,3000 3432.12,2300 TP14.1
  Bottom Layer w8: v2(2355,2975) 2460,2975 2485,3000 3345,3000 3370,2975 v1(3400,2975)
RI: U2.6
RST: J5.11 R8.1 S1.2 U3.58 | length 2402.7
  Top Layer w10: S1.2 R8.1 ; v1(3270.47,865.47) U3.58 ; J5.11 3600,1085 3619.53,1065.47 v1(3619.53,865.47)
  Bottom Layer w10: S1.2 2255,1200 2280,1225 3550,1225 J5.11 ; v1(3270.47,865.47) v1(3619.53,865.47)
RTS: U2.3
RX: U2.5 U3.32 | length 2809
  Top Layer w10: U2.5 v1(1175.59,831.41) ; v1(3445,410) 3445.87,410.87 3445.87,479.53 3445.87,493.77 3446.6,494.5 3447.64,494.5 U3.32
  Bottom Layer w10: v1(1175.59,831.41) 1175,832 1175.59,832 1959.11,832 2569.11,222 3257,222 v1(3445,410)
SLEEPN: J6.7 R107.1 TP22.1 U1.27 | length 7403.6
  Top Layer w10: U1.27 2273.31,3274.41 2288,3289.1 2288,3320.7 2310,3342.7 v2(2310,3360) ; v1(3420,3360) 3525,3255 3525,2965 4109,2381 4109,1641 J6.7 4329,1421 4329,669 4100.5,440.5 R107.1
  Kelvin w8: v2(2310,3360) 2340,3390 2340,4530 2710,4900 TP22.1
  Bottom Layer w10: v2(2310,3360) 2340,3390 2395,3390 2425,3360 v1(3420,3360)
SRN: J6.1 R101.1 TP13.1 U1.16 | length 5331.2
  Top Layer w8: U1.16 2282.09,2992.91 2335,2940 v2(2340,2940) ; v1(3400,2925) 3445.35,2925 3998,2372.35 3998,1134.36 R101.1@3866.64,1003 ; R101.1 R101.1@3866.64,1003 ; J6.1 4147,1003 R101.1@3866.64,1003
  Kelvin w8: v2(2340,2940) 2360,2940 3200,2100 TP13.1
  Bottom Layer w8: v2(2340,2940) 2495,2940 2512,2957 3278,2957 3311.5,2923.5 v1@3400,2923.5
STEP: J6.9 R109.1 TP16.1 U1.19 | length 6263.4
  Top Layer w8: U1.19 2289.68,3069.68 2315,3095 v2(2390,3095) ; v1(3600,3150) 3600,2945.71 4200,2345.71 J6.9 4371,1579 4371,511 4113,253 R109.1
  Kelvin w8: v2(2390,3095) 2435,3095 2450,3080 2697.37,3080 3077.37,2700 TP16.1
  Bottom Layer w8: v2(2390,3095) 2435,3095 2450,3080 3355,3080 3425,3150 v1(3600,3150)
TX: U2.1 U3.33 | length 3004.2
  Top Layer w10: U2.1 v1(1073.23,808.23) ; v1(3505,410) 3505,480 3520.47,495.47 U3.33
  Bottom Layer w10: v1(1073.23,808.23) 1075,810 1081.59,803.41 1956.59,803.41 2560,200 3295,200 v1(3505,410)
USBDM: J4.2 U2.16 | length 965.7
  Top Layer w10: v1(1370,880) 1370,925 1380.32,935.32 U2.16
  Bottom Layer w10: J4.2 649.21,950 900,950 990,860 1300,860 1320,880 v1(1370,880)
USBDP: J4.3 U2.15 | length 1059.1
  Top Layer w10: v1(1405,907.5) 1405.91,908.41 U2.15
  Bottom Layer w10: J4.3 595.47,975 910.36,975 1000.36,885 1285,885 1308,908 v1@1404.5,908
USM0: J6.3 R103.1 TP11.1 U1.13 | length 8434.4
  Top Layer w8: v1(1075,2960) 1075,1775 v1(1125,1725) ; v2(1880,2960) 1925,2960 1957.91,2992.91 U1.13@2000,2992.91 ; R103.1 4164.15,815.5 4257.53,908.87 4257.53,1087.47 J6.3@4197.5,1147.5 ; v1(4055,1725) 4030,1700 4030,1234 4114,1150 J6.3
  Kelvin w8: TP11.1 1077.33,2200 1762,2884.67 1762,2887 1835,2960 v2(1880,2960)
  Bottom Layer w8: v1(1075,2960) v2(1880,2960) ; v1(1125,1725) v1(4055,1725)
USM1: J6.4 R104.1 TP10.1 U1.12 | length 8647.7
  Top Layer w10: v1(975,1675) v1(975,3000) ; v2(1880,3000) 1935,3000 1953.5,3018.5 U1.12@2000,3018.5 ; R104.1 4094.44,721.75 4274.53,901.83 4274.53,1175.47 J6.4 4109,1250 4060,1299 v1@4060,1620
  Kelvin w8: TP10.1 1150,2400 1742,2992 1752.81,2992 1760.81,3000 v2(1880,3000)
  Bottom Layer w10: v1(975,1675) 1021,1629 v1@4060,1629 ; v1(975,3000) v2(1880,3000)
  other v1: 4060,1625
V3P3: C2.2 C15.2 C16.1 C17.2 C22.1 C23.2 JMP1.2 JP7.1 R4.1 R6.1 R8.2 R10.2 R11.2 TP25.1 U1.10 U2.4 U4.5 U4.6 | length 9381.7
  Top Layer w15: C2.2 1860,3100 v2(1880,3080) 1929.37,3080 1939.68,3069.68 U1.10@2000,3069.68
  Top Layer w25: R4.1 1345,3720 1275,3650 v1(1275,3120) 1275,2430 1225,2380 1225,2070 ; R6.1 1500,2085 1445,2030 1265,2030 1225,2070 ; 1575,660 1575,1100 v1(1225,1450) 1225,2070 ; v1(2030,1440) R8.2 ; JP7.1 2500,977 2552,925 C15.2 C16.1 v1(2850,1440) 2935,1525 C17.2 JMP1.2
  Kelvin w8: TP25.1 1500,2800 v1(1735,3035) 1780,3080 v2(1880,3080)
  Bottom Layer w25: v1(1225,1450) 1980,1450 1990,1440 v1(2030,1440) v1(2850,1440) ; v1(1275,3120) 1305,3090 1560,3090 1615,3035 v1(1735,3035)
VCP: C8.2 TP17.1 U1.22 | length 1932.2
  Top Layer w10: U1.22 2326.46,3146.46 v2(2340,3160) 2440,3160 2450,3150 C8.2
  Kelvin w8: v2(2340,3160) 2465,3160 2795,3490 2795,3765 2930,3900 TP17.1
VGD: C9.2 TP30.1 U1.20 | length 1745.1
  Top Layer w10: U1.20 2285.28,3095.28 2310,3120 v2(2340,3120) 2340.5,3120.5 2439.5,3120.5 C9.2
  Kelvin w8: v2(2340,3120) 2495,3120 2910,3535 3335,3535 TP30.1
VM: C1.2 C3.2 C4.1 C5.2 C8.1 D2.2 D3.2 D4.2 D5.2 J1.1 R3.2 TP24.1 U1.15 U1.28 | length 6301.6
  Top Layer w75: R3.2 TP24.1 J1.1 C3.2 C4.1 1220,4180 1460,4180 1755,4475 D2.2 2640,4355 2640,3870 ; C1.2 2345,2860 2405,2800 D5.2 2640,2920 ; C5.2 2243,3418 2702,3418 ; D4.2 2640,2320 2640,2920 ; D3.2 2635,3875 2640,3870 ; C8.1 2710,3150 2720,3160 ; 2640,2920 2720,3000 2720,3160 ; 2640,3870 2640,3480 2702,3418 ; 2702,3418 2720,3400 2720,3160
VREF: JP1.2 TP7.1 U1.8 | length 3078.9
  Top Layer w8: JP1.2 1560,3730 1560,3610 1355,3405 1355,3290 1380,3265 1380,3225 1365,3210 1365,3130 1375,3120 1575,3120 1615,3160 v2(1880,3160) 1918,3122 1998.87,3122 U1.8@2000,3120.87
  Kelvin w8: TP7.1 352,3148 1463,3148 1475,3160 v2(1880,3160)
pads on no net: J5.6 J5.8 J5.10 J5.12 J5.13 J5.14 U2.8 U2.24 U3.2 U3.3 U3.10 U3.11 U3.12 U3.13 U3.14 U3.15 U3.16 U3.17 U3.18 U3.19 U3.20 U3.21 U3.22 U3.23 U3.24 U3.25 U3.26 U3.27 U3.28 U3.29 U3.30 U3.31 U3.34 U3.35 U3.36 U3.38 U3.39 U3.48 U3.49 U3.50 U3.51 U3.52 U3.53 U3.59 U3.60 U3.61 U4.8

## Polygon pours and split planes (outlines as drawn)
GND on Top Layer "TOP-GND" (solid, remove dead copper, pour order 1008): 0,0 4500,0 4500,5500 100,5500 100,5400 0,5400
BOUT1 on Top Layer "BOUT1" (solid, pour order 1000): 1825,2985 1850,3010 1935,3010 1955,3030 2040,3030 2040,3060 1940,3060 1925,3075 1845,3075 1790,3020
AOUT1 on Top Layer "AOUT1" (solid, pour order 1001): 1770,3315 1875,3210 1980,3210 2040,3210 2040,3235 1965,3235 1960,3240 1910,3290 1880,3290 1865,3290 1805,3350 1770,3315
BOUT2 on Top Layer "BOUT2" (solid, pour order 1002): 2200,3030 2290,3030 2325,2995 2515,2995 2515,3075 2315,3075 2295,3055 2200,3055
AOUT2 on Top Layer "AOUT2" (solid, pour order 1003): 2200,3210 2360,3210 2395,3245 2485,3245 2485,3315 2340,3315 2265,3240 2200,3240
VM on Top Layer "VMA" (solid, remove dead copper, pour order 1004): 2200,2790 2175,2815 2175,2980 2315,2980 2315,2825 2280,2790
ISENB on Top Layer "ISENB" (solid, pour order 1005): 1930,2860 1930,2945 1960,2975 2075,2975 2075,2860 1930,2860
ISENA on Top Layer "ISENA" (solid, pour order 1006): 2035,3290 2035,3330 2045,3340 2070,3365 2070,3400 2070,3450 1925,3450 1925,3330 1965,3290 2035,3290
V3P3 on Top Layer "TOP-V3P3" (solid, pour order 1007): 800,0 800,700 2100,700 2100,0 800,0
GND on Kelvin "KLV-GND" (solid, remove dead copper, pour order 1010): 0,0 4500,0 4500,5500 0,5500 0,0
GND on Bottom Layer "BOT-GND" (solid, remove dead copper, pour order 1009): 0,0 4500,0 4500,5500 0,5500 0,0
GND on GND (split plane): 4479.9,20.1 20.1,20.1 20.1,5479.9 4479.9,5479.9
no net on InternalPlane2 (split plane): 4479.9,20.1 20.1,20.1 20.1,5479.9 4479.9,5479.9

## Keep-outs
Keep-Out Layer:
  lines w3.94: 0,100 100,100 100,0 ; 0,5400 100,5400 100,5500 ; 4400,0 4400,100 4500,100 ; 4400,5500 4400,5400 4500,5400
  lines w10: 0,0 0,5500 4500,5500 4500,0 0,0

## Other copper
Top Layer:
  rectangle net GND: 1920,2610 2080,2735
  rectangle net VM: 2205,3295 2275,3455
  rectangle net GND: 1925,3555 2075,3685
  text "Top Layer" at 4790,4820 h50
Kelvin:
  rectangle net GND: 2037,2942 2202,3348
  text "MidLayer1 - KELVIN" at 4800,4600 h50
MidLayer2:
  text "MidLayer2 - ALT-PWR" at 6385,4525 h50
Bottom Layer:
  text "BottomLayer" at 4800,4200 h50
GND (plane layer: these items are gaps in the copper):
  text "PLANE - GND" at 4800,4400 h50

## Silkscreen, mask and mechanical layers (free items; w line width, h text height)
Top Overlay:
  lines w10: 4790,3710 7490,3710 ; 1910,4286 2136,4286 2023,4399 1910,4286
  lines w15: 4673,234 4673,5364 cw(c4760,5364) 4760,5451 7482,5451 cw(c7482,5364) 7569,5364 7569,234 ; 4673,235 ccw(c4760,235) 4760,148 7482,148 ccw(c7482,235) 7569,235 ; 4730,5025 7506,5025 ; 4730,5215 7506,5215
  text "Layer Stack Up Detail for: DRV8818EVM" at 4735,5325 h50
  text "Layer Name" at 4740,5090 h50
  text "DRV8818 EVM" at 1980,4890 h60
  text "REV B 2/10/2012" at 2000,4720 h40
  text "VM" at 210,4582 h60
  text "!" at 2021,4305 h60
  text "WARNING" at 1832,4200 h60
  text "U1 may get hot" at 1715,4127 h48
  text "VREF SELECT" at 1580,3980 h40
  text "POT" at 1710,3885 h40
  text "SENSEA" at 1890,3710 h40
  text "INT" at 1700,3680 h40
  text "VREF" at 1370,3560 h40
  text "AO1" at 4450,3400 h60 r90
  text "AOUT1" at 3525,3275 h40
  text "AOUT2" at 3525,3175 h40
  text "AO2" at 4450,3175 h60 r90
  text "BOUT2" at 3525,3075 h40
  text "BOUT1" at 3525,2975 h40
  text "BO1" at 4450,2975 h60 r90
  text "BO2" at 4450,2750 h60 r90
  text "SENSEB" at 1890,2560 h40
  text "POT" at 1785,2335 h40
  text "INT" at 1775,2130 h40
  text "DECAY" at 1405,2005 h40
  text "Step" at 4268,1727 h40
  text "ENBLn" at 4264,1627 h40
  text "SLPn" at 4264,1528 h40
  text "Home" at 4264,1427 h40
  text "1" at 3020,1380 h40
  text "DIR" at 4265,1333 h40
  text "USM1" at 4268,1231 h40
  text "USB CONN" at 70,1180 h40
  text "STATUS" at 2300,1170 h40
  text "USM0" at 4265,1127 h40
  text "JTAG CONN" at 3080,1070 h40
  text "RSTn" at 4266,1036 h40
  text "SRn" at 4266,927 h40
  text "RESET" at 1950,850 h60
  text "3.3V" at 2060,550 h60
Mechanical 1:
  the board outline again, w3.94
Drill Drawing:
  text "Notes:" at 4790,3520 h60
  text "1.  NUMBER OF FINISHED LAYERS:  4" at 4790,3320 h60
  text "2.  BOARD MATERIAL AND CONSTRUCTION TO BE UL" at 4790,3120 h60
  text "APPROVED AND MARKED ON THE FINISHED BOARD." at 4990,2920 h60
  text "3.  LAMINATE MATERIAL: COPPER-CLAD FR-4" at 4790,2720 h60
  text "4.  COPPER WEIGHT: 1oz FINISHED" at 4790,2520 h60
  text "5.  FINISHED THICKNESS: .062 +/- .010" at 4790,2320 h60
  text "6.  MIN PLATING THICKNESS IN THROUGH HOLES: .001\"" at 4790,2120 h60
  text "7.  Gold Plating" at 4790,1920 h60
  text "8.  LPI SOLDERMASK BOTH SIDES USING APPROPRIATE" at 4790,1720 h60
  text "Drill Drawing." at 7700,1700 h40
  text "LAYER ARTWORK:  COLOR = RED" at 4990,1520 h60
  text ".LEGEND" at 7700,1500 h40
  text "9.  LPI SILKSCREEN AS REQUIRED:  COLOR - YELLOW" at 4805,1338 h60
  text "10.  VENDOR INFORMATION TO BE INCORPORATED" at 4790,1120 h60
  text "ON BACK SIDE WHENEVER POSSIBLE" at 4990,920 h60
  text "11.  MINIMUM COPPER CONDUCTOR WIDTH IS: 8 MILS" at 4790,720 h60
  text "12. MINIMUM CONDUCTOR SPACING IS: 8 MILS" at 4790,520 h60

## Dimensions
-100,5500 to -100,0 on Mechanical 1
0,5600 to 4500,5600 on Mechanical 1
